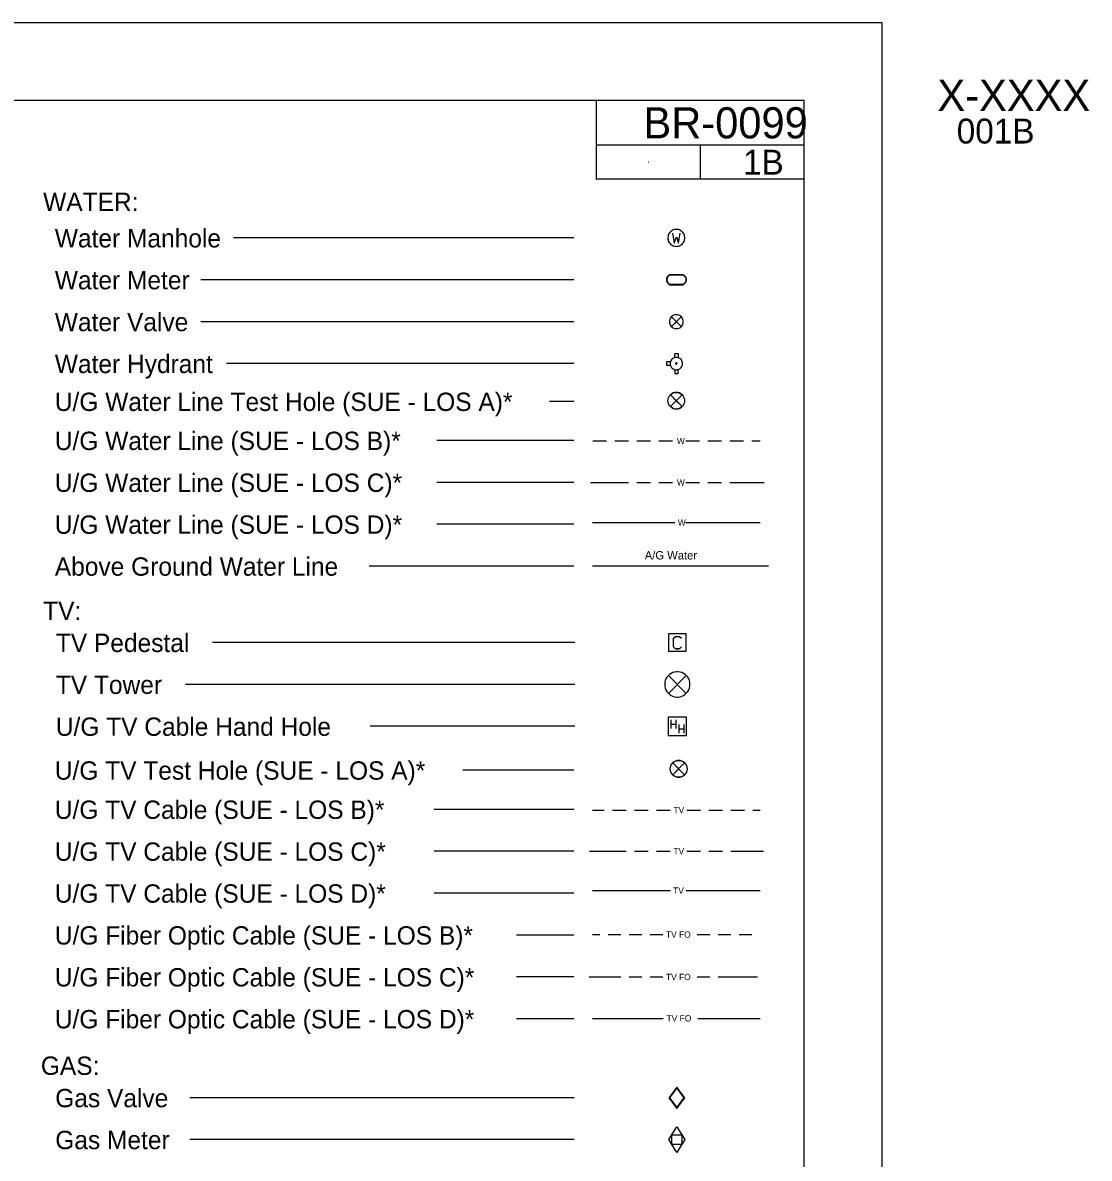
# Model space of a CAD drawing. Extents: x -0.53 to 3.34, y -0.27 to 4.33.
# Drawn here: x 2.361 to 3.217, y 3.417 to 4.328 of the extents above; entities that cross this region are included whole.
import ezdxf

# ---------------------------------------------------------------- set-up
doc = ezdxf.new("R2010")
doc.units = 0
for name, color, linetype in [('Exist Utilities TV Test Hole SUE LOS A CELL', 7, 'Continuous'), ('Exist Utilities Water Test Hole SUE LOS A CELL', 7, 'Continuous'), ('Sheet_Plan', 7, 'Continuous'), ('Sheet_Symbology', 7, 'Continuous'), ('Sheet_Title_Block_Text', 7, 'Continuous'), ('z - Construction', 7, 'Continuous')]:
    doc.layers.add(name, color=color, linetype=linetype)

msp = doc.modelspace()

# ---------------------------------------------------------------- linework, layer by layer
at = {"layer": 'Exist Utilities TV Test Hole SUE LOS A CELL'}
for points in [[(2.89214, 3.73421), (2.88264, 3.7247), (2.88739, 3.72946), (2.88264, 3.73421), (2.89214, 3.7247)], [(2.88264, 3.73421), (2.88739, 3.72946), (2.89214, 3.73421)], [(2.89214, 3.7247), (2.88739, 3.72946), (2.88264, 3.7247)]]:
    msp.add_lwpolyline(points, dxfattribs=at)
msp.add_circle((2.88739, 3.72946), 0.00672, dxfattribs=at)
for start, end in [(45, 135), (225, 315)]:
    msp.add_arc((2.88739, 3.72946), 0.00672, start, end, dxfattribs=at)
at = {"layer": 'Exist Utilities Water Test Hole SUE LOS A CELL'}
for points in [[(2.89022, 4.02974), (2.88072, 4.02024), (2.88547, 4.02499), (2.88072, 4.02974), (2.89022, 4.02024)], [(2.88072, 4.02974), (2.88547, 4.02499), (2.89022, 4.02974)], [(2.89022, 4.02024), (2.88547, 4.02499), (2.88072, 4.02024)]]:
    msp.add_lwpolyline(points, dxfattribs=at)
msp.add_circle((2.88547, 4.02499), 0.00672, dxfattribs=at)
for start, end in [(45, 135), (225, 315)]:
    msp.add_arc((2.88547, 4.02499), 0.00672, start, end, dxfattribs=at)
at = {"layer": 'Sheet_Plan'}
for p, q in [((2.98823, 4.26594), (0.2799, 4.26594)), ((2.82156, 4.20274), (2.82156, 4.26594)), ((2.98819, 2.55761), (2.98823, 4.26594)), ((2.98823, 4.23024), (2.82156, 4.23024)), ((2.9049, 4.20274), (2.9049, 4.23024)), ((2.98823, 4.20274), (2.82156, 4.20274))]:
    msp.add_line(p, q, dxfattribs=at)
msp.add_circle((2.82156, 4.20274), 0.0001, dxfattribs=at)
at = {"layer": 'Sheet_Symbology'}
for p, q in [((2.80311, 4.1557), (2.53005, 4.1557)), ((2.80311, 4.12207), (2.50373, 4.12207)), ((2.8804, 4.12639), (2.89073, 4.12639)), ((2.8804, 4.12606), (2.89073, 4.12606)), ((2.89066, 4.11816), (2.8804, 4.11816)), ((2.89066, 4.11782), (2.8804, 4.11782)), ((2.80311, 4.08844), (2.50373, 4.08844)), ((2.80311, 4.05481), (2.52433, 4.05481)), ((2.80311, 4.02439), (2.7837, 4.02439)), ((2.80311, 3.99304), (2.69317, 3.99304)), ((2.81854, 3.99268), (2.82947, 3.99268)), ((2.8362, 3.99268), (2.84713, 3.99268)), ((2.85385, 3.99268), (2.86478, 3.99268)), ((2.87151, 3.99268), (2.88244, 3.99268)), ((2.8932, 3.99268), (2.90413, 3.99268)), ((2.91086, 3.99268), (2.92179, 3.99268)), ((2.92851, 3.99268), (2.93944, 3.99268)), ((2.94617, 3.99268), (2.95279, 3.99268)), ((2.80311, 3.95941), (2.69317, 3.95941)), ((2.81663, 3.95941), (2.84713, 3.95941)), ((2.85385, 3.95941), (2.86478, 3.95941)), ((2.87151, 3.95941), (2.88244, 3.95941)), ((2.8932, 3.95941), (2.90413, 3.95941)), ((2.91086, 3.95941), (2.92179, 3.95941)), ((2.92851, 3.95941), (2.95594, 3.95941)), ((2.80311, 3.92578), (2.69317, 3.92578)), ((2.81827, 3.92725), (2.88435, 3.92725)), ((2.89276, 3.92725), (2.95279, 3.92725)), ((2.80311, 3.89215), (2.6388, 3.89215)), ((2.81827, 3.89251), (2.95954, 3.89251)), ((2.80392, 3.83086), (2.51315, 3.83086)), ((2.88528, 3.82592), (2.88745, 3.82592)), ((2.80392, 3.79723), (2.49141, 3.79723)), ((2.88118, 3.76869), (2.88118, 3.76191)), ((2.88118, 3.76524), (2.88505, 3.76524)), ((2.88505, 3.76869), (2.88505, 3.76191)), ((2.88765, 3.765), (2.88765, 3.75822)), ((2.89152, 3.765), (2.89152, 3.75822)), ((2.80392, 3.7636), (2.63961, 3.7636)), ((2.88765, 3.76155), (2.89152, 3.76155)), ((2.80311, 3.7284), (2.71422, 3.7284)), ((2.80311, 3.69693), (2.69098, 3.69693)), ((2.81827, 3.69639), (2.82764, 3.69639)), ((2.83437, 3.69639), (2.8453, 3.69639)), ((2.85202, 3.69639), (2.86295, 3.69639)), ((2.86968, 3.69639), (2.88061, 3.69639)), ((2.89406, 3.69639), (2.90499, 3.69639)), ((2.91172, 3.69639), (2.92265, 3.69639)), ((2.92938, 3.69639), (2.94031, 3.69639)), ((2.94703, 3.69639), (2.95279, 3.69639)), ((2.80311, 3.6633), (2.69098, 3.6633)), ((2.81594, 3.6633), (2.8453, 3.6633)), ((2.85202, 3.6633), (2.86295, 3.6633)), ((2.86968, 3.6633), (2.88061, 3.6633)), ((2.89406, 3.6633), (2.90499, 3.6633)), ((2.91172, 3.6633), (2.92265, 3.6633)), ((2.92938, 3.6633), (2.95562, 3.6633)), ((2.80311, 3.62967), (2.69098, 3.62967)), ((2.81827, 3.6317), (2.88078, 3.6317)), ((2.89339, 3.6317), (2.95279, 3.6317)), ((2.80311, 3.59604), (2.75731, 3.59604)), ((2.81827, 3.59644), (2.82415, 3.59644)), ((2.83088, 3.59644), (2.84097, 3.59644)), ((2.84769, 3.59644), (2.85778, 3.59644)), ((2.86451, 3.59644), (2.8746, 3.59644)), ((2.90235, 3.59644), (2.91243, 3.59644)), ((2.91916, 3.59644), (2.92925, 3.59644)), ((2.93598, 3.59644), (2.94607, 3.59644)), ((2.80311, 3.5624), (2.75731, 3.5624)), ((2.81551, 3.5624), (2.84097, 3.5624)), ((2.84769, 3.5624), (2.85778, 3.5624)), ((2.86451, 3.5624), (2.8746, 3.5624)), ((2.90235, 3.5624), (2.91243, 3.5624)), ((2.91916, 3.5624), (2.95066, 3.5624)), ((2.80311, 3.52877), (2.75731, 3.52877)), ((2.81827, 3.52917), (2.87508, 3.52917)), ((2.90283, 3.52917), (2.95279, 3.52917)), ((2.88587, 3.47337), (2.87996, 3.46543)), ((2.89178, 3.46543), (2.88587, 3.47337)), ((2.80346, 3.46543), (2.49491, 3.46543)), ((2.87996, 3.46543), (2.88587, 3.4575)), ((2.88587, 3.4575), (2.89178, 3.46543)), ((2.80346, 3.4318), (2.49491, 3.4318))]:
    msp.add_line(p, q, dxfattribs=at)
for points in [[(2.88553, 4.16253), (2.88466, 4.16247), (2.88384, 4.16231), (2.88302, 4.16204), (2.88225, 4.16166), (2.88154, 4.16122), (2.88089, 4.16067), (2.88028, 4.16002), (2.87979, 4.15936), (2.87936, 4.1586), (2.87908, 4.15778), (2.87887, 4.15696), (2.87876, 4.15614), (2.87876, 4.15527), (2.87887, 4.15445), (2.87908, 4.15357), (2.87936, 4.15281), (2.87979, 4.15204), (2.88028, 4.15139), (2.88089, 4.15073), (2.88154, 4.15019), (2.88225, 4.14975), (2.88302, 4.14937), (2.88384, 4.14909), (2.88471, 4.14893), (2.88553, 4.14888), (2.8864, 4.14893), (2.88722, 4.14909), (2.88804, 4.14937), (2.88881, 4.14975), (2.88952, 4.15019), (2.89017, 4.15073), (2.89077, 4.15139), (2.89127, 4.15204), (2.8917, 4.15281), (2.89197, 4.15363), (2.89219, 4.15445), (2.8923, 4.15527), (2.8923, 4.15614), (2.89219, 4.15696), (2.89197, 4.15783), (2.8917, 4.1586), (2.89127, 4.15936), (2.89077, 4.16002), (2.89017, 4.16067), (2.88952, 4.16122), (2.88881, 4.16166), (2.88804, 4.16204), (2.88722, 4.16231), (2.88635, 4.16247), (2.88553, 4.16253)], [(2.88247, 4.15947), (2.88389, 4.1515), (2.88553, 4.15652), (2.88722, 4.1515), (2.88864, 4.15947)], [(2.8804, 4.12639), (2.87972, 4.12606), (2.87911, 4.12558), (2.87857, 4.12498), (2.87817, 4.12437), (2.87783, 4.12362), (2.87763, 4.12288), (2.87756, 4.12214), (2.87763, 4.12133), (2.87783, 4.12059), (2.87817, 4.11991), (2.87857, 4.11923), (2.87911, 4.11869), (2.87972, 4.11822), (2.8804, 4.11782)], [(2.88053, 4.12612), (2.87986, 4.12572), (2.87925, 4.12525), (2.87871, 4.12464), (2.8783, 4.12403), (2.87803, 4.12329), (2.8779, 4.12248), (2.8779, 4.12173), (2.87803, 4.12099), (2.8783, 4.12025), (2.87871, 4.11957), (2.87925, 4.11896), (2.87986, 4.11849), (2.88053, 4.11816)], [(2.89053, 4.12612), (2.89127, 4.12579), (2.89188, 4.12525), (2.89235, 4.1247), (2.89276, 4.12403), (2.89303, 4.12329), (2.89316, 4.12248), (2.89316, 4.12173), (2.89303, 4.12092), (2.89276, 4.12025), (2.89235, 4.11957), (2.89181, 4.11896), (2.8912, 4.11849), (2.89053, 4.11809)], [(2.89066, 4.12639), (2.89134, 4.12606), (2.89194, 4.12558), (2.89249, 4.12498), (2.89289, 4.12437), (2.89323, 4.12362), (2.89343, 4.12288), (2.8935, 4.12214), (2.89343, 4.12133), (2.89323, 4.12059), (2.89289, 4.11991), (2.89249, 4.11923), (2.89194, 4.11869), (2.89134, 4.11822), (2.89066, 4.11782)], [(2.89111, 4.08844), (2.89105, 4.08925), (2.89087, 4.09012), (2.89056, 4.09086), (2.89012, 4.09161), (2.88962, 4.09223), (2.889, 4.09279), (2.88832, 4.09328), (2.88758, 4.09365), (2.88677, 4.0939), (2.88596, 4.09402), (2.88509, 4.09402), (2.88429, 4.0939), (2.88348, 4.09365), (2.88274, 4.09328), (2.88205, 4.09279), (2.88143, 4.09223), (2.88094, 4.09161), (2.8805, 4.09086), (2.88019, 4.09012), (2.88001, 4.08925), (2.87994, 4.08844), (2.88001, 4.08763), (2.88019, 4.08676), (2.8805, 4.08602), (2.88094, 4.08527), (2.88143, 4.08465), (2.88205, 4.08409), (2.88274, 4.0836), (2.88348, 4.08323), (2.88429, 4.08298), (2.88509, 4.08286), (2.88596, 4.08286), (2.88677, 4.08298), (2.88758, 4.08323), (2.88832, 4.0836), (2.889, 4.08409), (2.88962, 4.08465), (2.89012, 4.08527), (2.89056, 4.08602), (2.89087, 4.08676), (2.89105, 4.08763), (2.89111, 4.08844)], [(2.8895, 4.08447), (2.88156, 4.09241), (2.88553, 4.08844), (2.88156, 4.08447), (2.8895, 4.09241)], [(2.88547, 4.05978), (2.88469, 4.05971), (2.88392, 4.05952), (2.88314, 4.0592), (2.8825, 4.05875), (2.88192, 4.05823), (2.8814, 4.05758), (2.88101, 4.05687), (2.88075, 4.0561), (2.88056, 4.05533), (2.88056, 4.05455), (2.88069, 4.05378), (2.88088, 4.053), (2.88127, 4.05229), (2.88172, 4.05165), (2.8823, 4.05107), (2.88295, 4.05055), (2.88366, 4.05023), (2.88443, 4.04997), (2.88521, 4.04984), (2.88598, 4.04984), (2.88676, 4.04997), (2.88753, 4.05029), (2.88824, 4.05061), (2.88889, 4.05113), (2.8894, 4.05171), (2.88985, 4.05235), (2.89018, 4.05313), (2.89043, 4.05391), (2.8905, 4.05468), (2.89043, 4.05546), (2.8903, 4.05623), (2.88998, 4.057), (2.8896, 4.05771), (2.88908, 4.0583), (2.88844, 4.05881), (2.88779, 4.05926), (2.88701, 4.05952), (2.88624, 4.05971), (2.88547, 4.05978)], [(2.8843, 4.05965), (2.8843, 4.06288), (2.88688, 4.06288), (2.88688, 4.05958)], [(2.88075, 4.0561), (2.87753, 4.0561), (2.87753, 4.05352), (2.88075, 4.05352)], [(2.8843, 4.04997), (2.8843, 4.04674), (2.88688, 4.04674), (2.88688, 4.05003)], [(2.88553, 4.05539), (2.88527, 4.05533), (2.88508, 4.05513), (2.88495, 4.05487), (2.88501, 4.05461), (2.88514, 4.05436), (2.8854, 4.05423), (2.88566, 4.05423), (2.88592, 4.05436), (2.88605, 4.05461), (2.88611, 4.05487), (2.88598, 4.05513), (2.88579, 4.05533), (2.88553, 4.05539)], [(2.87933, 3.82386), (2.89334, 3.82386), (2.89334, 3.83787), (2.87933, 3.83787), (2.87933, 3.82386)], [(2.88961, 3.82747), (2.88795, 3.82592), (2.88472, 3.82592), (2.88316, 3.82747), (2.88316, 3.83426), (2.88472, 3.83581), (2.88795, 3.83581), (2.88961, 3.83426)], [(2.89646, 3.79723), (2.89635, 3.7987), (2.89601, 3.80027), (2.89545, 3.80162), (2.89466, 3.80297), (2.89376, 3.8041), (2.89264, 3.80511), (2.8914, 3.80601), (2.89005, 3.80669), (2.88858, 3.80714), (2.88712, 3.80736), (2.88554, 3.80736), (2.88408, 3.80714), (2.88262, 3.80669), (2.88127, 3.80601), (2.88003, 3.80511), (2.87891, 3.8041), (2.87801, 3.80297), (2.87722, 3.80162), (2.87665, 3.80027), (2.87632, 3.7987), (2.87621, 3.79723), (2.87632, 3.79577), (2.87665, 3.79419), (2.87722, 3.79285), (2.87801, 3.79149), (2.87891, 3.79037), (2.88003, 3.78935), (2.88127, 3.78845), (2.88262, 3.78778), (2.88408, 3.78733), (2.88554, 3.78711), (2.88712, 3.78711), (2.88858, 3.78733), (2.89005, 3.78778), (2.8914, 3.78845), (2.89264, 3.78935), (2.89376, 3.79037), (2.89466, 3.79149), (2.89545, 3.79285), (2.89601, 3.79419), (2.89635, 3.79577), (2.89646, 3.79723)], [(2.89354, 3.79003), (2.87913, 3.80444), (2.88633, 3.79723), (2.87913, 3.79003), (2.89354, 3.80444)], [(2.87909, 3.75636), (2.89357, 3.75636), (2.89357, 3.77084), (2.87909, 3.77084), (2.87909, 3.75636)], [(2.88587, 3.47404), (2.87946, 3.46543), (2.88587, 3.45682), (2.89229, 3.46543), (2.88587, 3.47404)], [(2.87946, 3.4318), (2.88587, 3.44218), (2.89229, 3.4318), (2.88587, 3.42142), (2.87946, 3.4318)], [(2.88191, 3.43568), (2.88984, 3.43568), (2.88984, 3.42783), (2.88191, 3.42783), (2.88191, 3.43568)]]:
    msp.add_lwpolyline(points, dxfattribs=at)
at = {"layer": 'z - Construction'}
for p, q in [((3.05073, 4.32844), (0.2174, 4.32844)), ((3.05073, 2.49511), (3.05073, 4.32844))]:
    msp.add_line(p, q, dxfattribs=at)
for centre in [(2.9049, 4.24809), (2.86323, 4.21649), (2.94656, 4.21649)]:
    msp.add_circle(centre, 0.0001, dxfattribs=at)

# ---------------------------------------------------------------- texts
at = {"layer": 'Sheet_Symbology'}
for s, height, p in [('WATER:', 0.014714, (2.37722, 4.17729)), ('Water Manhole', 0.0147137, (2.38659, 4.14807)), ('Water Meter', 0.0147137, (2.38659, 4.11444)), ('Water Valve', 0.0147137, (2.38659, 4.08081)), ('Water Hydrant', 0.0147137, (2.38659, 4.04718)), ('U/G Water Line Test Hole (SUE - LOS A)*', 0.0147137, (2.38659, 4.01676)), ('U/G Water Line (SUE - LOS B)*', 0.0147137, (2.38659, 3.98541)), ('W', 0.00504, (2.88597, 3.99015)), ('U/G Water Line (SUE - LOS C)*', 0.0147137, (2.38659, 3.95178)), ('W', 0.00504, (2.88597, 3.95689)), ('U/G Water Line (SUE - LOS D)*', 0.0147137, (2.38659, 3.91815)), ('W', 0.00504, (2.88671, 3.92473)), ('A/G Water', 0.006726, (2.86018, 3.89755)), ('Above Ground Water Line', 0.0147137, (2.38659, 3.88452)), ('TV:', 0.014714, (2.37722, 3.84893)), ('TV Pedestal', 0.0147137, (2.38739, 3.82323)), ('TV Tower', 0.014714, (2.38739, 3.7896)), ('U/G TV Cable Hand Hole', 0.0147137, (2.38739, 3.75597)), ('U/G TV Test Hole (SUE - LOS A)*', 0.0147137, (2.38659, 3.72077)), ('U/G TV Cable (SUE - LOS B)*', 0.0147137, (2.38659, 3.6893)), ('TV', 0.005045, (2.88322, 3.69386)), ('U/G TV Cable (SUE - LOS C)*', 0.0147137, (2.38659, 3.65567)), ('TV', 0.005045, (2.88322, 3.66078)), ('U/G TV Cable (SUE - LOS D)*', 0.0147137, (2.38659, 3.62204)), ('TV', 0.005045, (2.88297, 3.62918)), ('U/G Fiber Optic Cable (SUE - LOS B)*', 0.0147137, (2.38659, 3.5884)), ('TV FO', 0.005045, (2.87721, 3.59392)), ('U/G Fiber Optic Cable (SUE - LOS C)*', 0.0147137, (2.38659, 3.55477)), ('TV FO', 0.005045, (2.87721, 3.55988)), ('U/G Fiber Optic Cable (SUE - LOS D)*', 0.0147137, (2.38659, 3.52114)), ('TV FO', 0.005045, (2.87769, 3.52665)), ('GAS:', 0.014714, (2.37538, 3.4838)), ('Gas Valve', 0.014714, (2.38693, 3.4578)), ('Gas Meter', 0.014714, (2.38693, 3.42417))]:
    msp.add_text(s, height=height, dxfattribs=at).set_placement(p)
at = {"layer": 'Sheet_Title_Block_Text'}
for s, height, p in [('X-XXXX', 0.025, (3.09511, 4.25763)), ('BR-0099', 0.025, (2.8591, 4.23559)), ('001B', 0.02, (3.11061, 4.23146)), ('1B', 0.02, (2.93901, 4.20649))]:
    msp.add_text(s, height=height, dxfattribs=at).set_placement(p)

doc.saveas('drawing.dxf')
